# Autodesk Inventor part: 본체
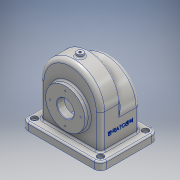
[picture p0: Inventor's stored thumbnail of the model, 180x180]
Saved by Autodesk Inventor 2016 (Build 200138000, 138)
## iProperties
Created: 2017-11
Part Number: 본체
Material: 알루미늄 6061
Document SubType Name: Modeling
Designer: USER
Density: 2.7 g/cm^3
Appearance: 알루미늄 - 평지
Mass: 1075.5 g
Surface Area: 1182.07 cm^2
Volume: 398.334 cm^3
Author: USER
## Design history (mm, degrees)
sketch "스케치1"
  geometry: L1 (-58, 0)-(-58, -80); L2 (-58, -80)-(58, -80); L3 (58, -80)-(58, 0); A1 r 58 centre (0, 0) between (58, 0) and (-58, 0); 2 further points
  constraints: 6 end point, 2 point on circle, 2 tangent, 1 centre point, 1 coincident, 1 horizontal alignment, 1 midpoint, 1 perpendicular, 1 vertical
  dimensions: "d0" = 116 diameter of A1; "d2" = 116 distance of L1.end L2.end; "d3" = 80 distance from line of L2 point (0, 0)
extrude "돌출1" new body sketch "스케치1" distance "d4" = 38; taper "d5" = 0 deg
sketch "스케치2"
  geometry: L1 (58, 80)-(-58, 80) reference; L2 (58, 0)-(58, 80) reference; L3 (58, 23)-(58, 80); L4 (58, 80)-(-58, 80); L5 (-58, 80)-(-58, 0) reference; L6 (-58, 23)-(-58, 80); A1 r 58 centre (0, 23) between (-58, 23) and (58, 23); 1 further point
  constraints: 6 end point, 2 collinear, 2 point on circle, 1 centre point, 1 vertical alignment
  dimensions: "d7" = 57 distance from line of L1 A1.centre; "d9" = 58 radius of A1; "d10" = 57 distance of L3.start L1.start
extrude "돌출2" join sketch "스케치2" distance "d11" = 38; taper "d12" = 0 deg
feature "쉘1" dims "d13" = 5
sketch "스케치3"
  geometry: L1 (133, -17)-(-17, -17); L2 (-17, -17)-(-17, 93); L3 (-17, 93)-(133, 93); L4 (133, 93)-(133, -17); L5 (5, 71)-(111, 71) reference; L6 (111, 71)-(111, 5) reference; L7 (111, 5)-(5, 5) reference; L8 (5, 5)-(5, 71) reference; L9 (116, 0)-(0, 0) reference; L10 (116, 0)-(116, 76) reference; L11 (0, 76)-(116, 76) reference; L12 (0, 0)-(0, 76) reference; 5 further points
  constraints: 8 end point, 4 midpoint, 2 parallel, 1 horizontal, 1 horizontal alignment, 1 perpendicular, 1 vertical alignment
  dimensions: "d14" = 150 distance of L1.start L1.end; "d15" = 110 distance of L1.end L2.end
extrude "돌출3" join sketch "스케치3" distance "d16" = 15; taper "d17" = 0 deg
sketch "스케치4"
  geometry: L1 (75, 80)-(-75, 80) reference; C1 r 31 at (0, 15); 1 further point
  constraints: 1 centre point, 1 vertical alignment
  dimensions: "d18" = 62 diameter of C1; "d19" = 65 distance from line of L1 C1.centre
extrude "돌출4" join sketch "스케치4" distance "d20" = 10; taper "d21" = 0 deg
sketch "스케치5"
  geometry: L1 (-75, -80)-(75, -80) reference; C1 r 37.5 at (0, -15); 1 further point
  constraints: 1 centre point, 1 vertical alignment
  dimensions: "d22" = 75 diameter of C1; "d23" = 65 distance from line of L1 C1.centre
extrude "돌출5" join sketch "스케치5" distance "d24" = 9; taper "d25" = 0 deg
sketch "스케치6"
  geometry: L1 (75, 65)-(-75, 65) reference; C1 r 16 at (0, 0); 1 further point
  constraints: 1 centre point, 1 vertical alignment
  dimensions: "d26" = 32 diameter of C1; "d27" = 65 distance from line of L1 C1.centre
extrude "돌출6" cut sketch "스케치6" distance "d28" = 107.75; taper "d29" = 0 deg
sketch "스케치7"
  geometry: C1 r 16 at (0, 0) reference; C2 r 37.5 at (0, 0) reference; 2 further points
  constraints: 1 vertical alignment
  dimensions: "d30" = 29 distance of C1.centre point (0, 29)
hole "구멍1" sketch "스케치7" at (0, 29) diameter "d31" = 2.459; stored, may be unused: countersink angle "d35" = 90 deg, drill point angle "d37" = 118 deg; dims "d32" = 6, "d33" = 4, "d34" = 2, "d36" = 8
sketch "스케치8"
  geometry: C1 r 16 at (0, 0) reference; C2 r 31 at (0, 0) reference; 2 further points
  constraints: 1 vertical alignment
  dimensions: "d42" = 26 distance of point (0, -26) C1.centre
hole "구멍2" sketch "스케치8" at (0, -26) diameter "d43" = 2.459; stored, may be unused: countersink angle "d47" = 90 deg, drill point angle "d49" = 118 deg; dims "d44" = 6, "d45" = 4, "d46" = 2, "d48" = 8
sketch "스케치9"
  geometry: L1 (-133, 93)-(-133, -17) reference; L2 (17, 93)-(-133, 93) reference; L3 (17, -17)-(17, 93) reference; L4 (-133, -17)-(17, -17) reference; C1 r 6 at (-121, 81); C2 r 6 at (5, 81); C3 r 6 at (5, -5); C4 r 6 at (-121, -5); 1 further point
  constraints: 4 centre point, 2 horizontal alignment, 2 vertical alignment
  dimensions: "d53" = 12 diameter of C1; "d54" = 12 diameter of C2; "d55" = 12 diameter of C3; "d56" = 12 diameter of C4; "d57" = 12 distance from line of L1 C1.centre; "d58" = 12 distance from line of L2 C1.centre; "d59" = 12 distance from line of C3.centre L3; "d60" = 12 distance from line of L4 C3.centre
fillet "모깎기1" dims "d61" = 12
fillet "모깎기2" dims "d62" = 8
fillet "모깎기3" dims "d63" = 3
extrude "돌출7" cut sketch "스케치9" distance "d64" = 5; taper "d65" = 0 deg
sketch "스케치10"
  geometry: C1 r 6 at (126, -98) reference; C2 r 2.5 at (126, -98); C3 r 6 at (0, -12) reference; C4 r 2.5 at (0, -12); C5 r 2.5 at (0, -98); C6 r 2.5 at (126, -12); 1 further point
  constraints: 4 centre point, 2 coincident, 2 horizontal alignment, 2 vertical alignment
  dimensions: "d66" = 5 diameter of C2; "d67" = 5 diameter of C4; "d68" = 5 diameter of C5; "d69" = 5 diameter of C6
extrude "돌출8" cut sketch "스케치10" distance "d70" = 114.25; taper "d71" = 0 deg
fillet "모깎기4" dims "d72" = 3
fillet "모깎기5" dims "d73" = 3
node "작업 평면1"
sketch "스케치11"
  geometry: L1 (113, -93)-(13, -93) reference; L2 (138, -12)-(138, -98) reference; C1 r 6 at (63, -74); 1 further point
  constraints: 1 centre point
  dimensions: "d75" = 12 diameter of C1; "d76" = 19 distance from line of L1 C1.centre; "d77" = 75 distance from line of C1.centre L2
extrude "돌출9" join sketch "스케치11" distance "d78" = 7.5; taper "d79" = 0 deg
fillet "모깎기6" dims "d80" = 3
sketch "스케치12"
  geometry: C1 r 6 at (0, 0) reference; 2 further points
  constraints: 1 coincident
hole "구멍3" sketch "스케치12" at (0, 0) diameter "d81" = 4.459; stored, may be unused: countersink angle "d85" = 90 deg, drill point angle "d87" = 118 deg; dims "d82" = 10, "d83" = 4, "d84" = 2, "d86" = 24.5469
fillet "모깎기7" dims "d88" = 3
fillet "모깎기8" dims "d89" = 3
sketch "스케치13"
  geometry: L1 (-23, -35)-(39, -35) reference; L2 (57, -40)-(57, -52) reference; 1 further point
  constraints: 1 other
  dimensions: "d90" = 38 distance from line of L1 point (17, 3); "d91" = 40 distance from line of L2 point (17, 3)
feature "엠보싱1" sketch "스케치13" dims "d92" = 0.5, "d93" = 0
chamfer "모따기1" distance "d94" = 1; stored, may be unused: second distance "d95" = 2, angle "d96" = 45 deg
node "솔리드1"
pattern_circular "원형 패턴1" dims angle "d39" = 360 deg
pattern_circular "원형 패턴2" dims angle "d51" = 360 deg
node "투영된 루프1"
node "투영된 루프2"
node "투영된 루프3"
node "투영된 루프4"
other parameters: "d6" = 116, "d74" = -144
